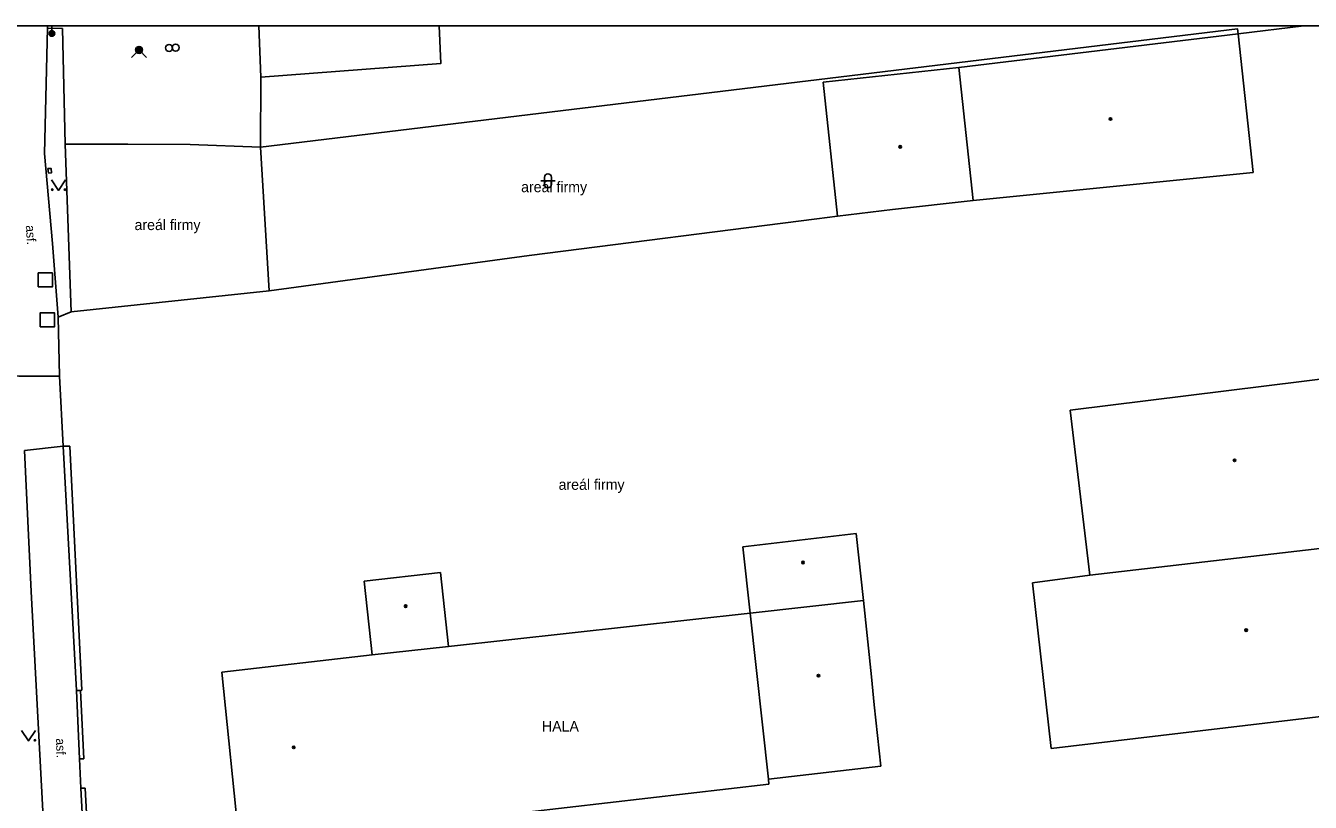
# Model space of a CAD drawing. Extents: x -599951 to -598963, y -1164095 to -1162939.
# Drawn here: x -599227.9 to -599136.7, y -1162994.5 to -1162939.4 of the extents above; entities that cross this region are included whole.
import ezdxf

# ---------------------------------------------------------------- set-up
doc = ezdxf.new("R2010")
doc.units = 0
for name, color, linetype in [('Level 10', 7, 'Continuous'), ('Level 11', 7, 'Continuous'), ('Level 24', 7, 'Continuous'), ('Level 26', 7, 'Continuous'), ('Level 28', 7, 'Continuous'), ('Level 31', 7, 'Continuous'), ('Level 33', 7, 'Continuous'), ('Level 36', 7, 'Continuous'), ('Level 39', 7, 'Continuous'), ('Level 40', 7, 'Continuous'), ('Level 41', 7, 'Continuous'), ('Level 42', 7, 'Continuous'), ('Level 5', 7, 'Continuous'), ('Level 51', 7, 'Continuous'), ('Level 52', 7, 'Continuous'), ('Level 7', 7, 'Continuous'), ('Level 8', 7, 'Continuous'), ('Vrstva 53', 7, 'Continuous')]:
    doc.layers.add(name, color=color, linetype=linetype)

msp = doc.modelspace()

# ---------------------------------------------------------------- linework, layer by layer
at = {"layer": 'Level 10'}
msp.add_line((-599226.356, -1162939.4), (-599226.36, -1162939.58), dxfattribs=at)
for points in [[(-599226.36, -1162939.58), (-599225.29, -1162939.6), (-599225.09, -1162947.8)], [(-599225.5, -1162964.29), (-599228.38, -1162964.28), (-599229.19, -1162964.24)], [(-599225.23, -1162969.24), (-599227.97, -1162969.57)]]:
    msp.add_lwpolyline(points, dxfattribs=at)
at = {"layer": 'Level 11'}
for points in [[(-599226.36, -1162939.58), (-599226.38, -1162940.54), (-599226.55, -1162948.47)], [(-599211.21, -1162943.06), (-599198.43, -1162942.09), (-599198.548, -1162939.4)], [(-599226.55, -1162948.47), (-599225.99, -1162954.86)], [(-599227.97, -1162969.57), (-599227.51, -1162979.56), (-599226.57, -1162997.39)]]:
    msp.add_lwpolyline(points, dxfattribs=at)
at = {"layer": 'Level 24'}
for points in [[(-599226.32, -1162949.55), (-599226.1, -1162949.53), (-599226.07, -1162949.85), (-599226.28, -1162949.87)], [(-599226.32, -1162949.55), (-599226.28, -1162949.87)]]:
    msp.add_lwpolyline(points, dxfattribs=at)
at = {"layer": 'Level 26'}
for points in [[(-599227, -1162957.95), (-599226, -1162957.95), (-599226, -1162956.95), (-599227, -1162956.95)], [(-599226.86, -1162960.78), (-599225.86, -1162960.78), (-599225.86, -1162959.78), (-599226.86, -1162959.78)]]:
    msp.add_lwpolyline(points, close=True, dxfattribs=at)
at = {"layer": 'Level 28'}
for centre in [(-599217.72, -1162940.98), (-599217.25, -1162940.96)]:
    msp.add_circle(centre, 0.25, dxfattribs=at)
at = {"layer": 'Level 31'}
msp.add_lwpolyline([(-599220.38, -1162941.65), (-599219.85, -1162941.12), (-599219.32, -1162941.65)], dxfattribs=at)
for radius in [0.25, 0.18, 0.11]:
    msp.add_circle((-599219.85, -1162941.12), radius, dxfattribs=at)
at = {"layer": 'Level 33'}
msp.add_line((-599226.03, -1162939.4), (-599226.03, -1162939.95), dxfattribs=at)
for radius in [0.2, 0.145, 0.0876]:
    msp.add_circle((-599226.03, -1162939.95), radius, dxfattribs=at)
at = {"layer": 'Level 36'}
for p, q in [((-599191.326, -1162950.416), (-599190.326, -1162950.416)), ((-599191.076, -1162950.166), (-599191.076, -1162950.666)), ((-599190.576, -1162950.166), (-599190.576, -1162950.666))]:
    msp.add_line(p, q, dxfattribs=at)
for points in [[(-599226.06, -1162950.34), (-599225.56, -1162951.09), (-599225.06, -1162950.34)], [(-599228.19, -1162989.43), (-599227.69, -1162990.18), (-599227.19, -1162989.43)]]:
    msp.add_lwpolyline(points, dxfattribs=at)
for centre in [(-599226.01, -1162951.04), (-599225.111, -1162951.04), (-599227.241, -1162990.13)]:
    msp.add_circle(centre, 0.05, dxfattribs=at)
for centre, start, end in [((-599190.826, -1162950.166), 0, 180), ((-599190.826, -1162950.666), 180, 0)]:
    msp.add_arc(centre, 0.25, start, end, dxfattribs=at)
at = {"layer": 'Level 39'}
for centre, radius in [((-599150.9, -1162946.02), 0.09), ((-599150.9, -1162946.02), 0.0398), ((-599165.82, -1162948), 0.09), ((-599165.82, -1162948), 0.0398), ((-599142.09, -1162970.26), 0.09), ((-599142.09, -1162970.26), 0.0398), ((-599172.72, -1162977.51), 0.09), ((-599172.72, -1162977.51), 0.0398), ((-599200.93, -1162980.61), 0.09), ((-599200.93, -1162980.61), 0.0398), ((-599141.27, -1162982.31), 0.09), ((-599141.27, -1162982.31), 0.0398), ((-599171.62, -1162985.54), 0.09), ((-599171.62, -1162985.54), 0.0398), ((-599208.87, -1162990.63), 0.09), ((-599208.87, -1162990.63), 0.0398)]:
    msp.add_circle(centre, radius, dxfattribs=at)
at = {"layer": 'Level 5'}
for points in [[(-599177, -1162976.4), (-599168.94, -1162975.45)], [(-599168.94, -1162975.45), (-599168.43, -1162980.21)], [(-599176.48, -1162981.1), (-599177, -1162976.4)], [(-599203.88, -1162978.83), (-599198.45, -1162978.23)], [(-599198.45, -1162978.23), (-599197.88, -1162983.47)], [(-599203.3, -1162984.07), (-599203.88, -1162978.83)], [(-599176.48, -1162981.1), (-599168.43, -1162980.21)], [(-599168.43, -1162980.21), (-599167.85, -1162985.62)], [(-599197.88, -1162983.47), (-599176.48, -1162981.1)], [(-599176.48, -1162981.1), (-599175.17, -1162992.89)], [(-599203.3, -1162984.07), (-599197.88, -1162983.47)], [(-599213.97, -1162985.29), (-599203.3, -1162984.07)], [(-599213.97, -1162985.29), (-599212.72, -1162997.59)], [(-599167.85, -1162985.62), (-599167.67, -1162987.62)], [(-599167.67, -1162987.62), (-599167.2, -1162991.97)], [(-599167.2, -1162991.97), (-599175.17, -1162992.89)], [(-599175.15, -1162993.25), (-599212.36, -1162997.55), (-599212.72, -1162997.59)], [(-599175.17, -1162992.89), (-599175.15, -1162993.25)]]:
    msp.add_lwpolyline(points, dxfattribs=at)
at = {"layer": 'Level 51'}
msp.add_line((-599137.179, -1162939.4), (-599141.84, -1162939.97), dxfattribs=at)
for points in [[(-599211.23, -1162948.02), (-599141.89, -1162939.62), (-599141.84, -1162939.97)], [(-599170.27, -1162952.93), (-599171.73, -1162953.11), (-599192.16, -1162955.72), (-599210.62, -1162958.23)]]:
    msp.add_lwpolyline(points, dxfattribs=at)
at = {"layer": 'Level 52'}
for points in [[(-599161.66, -1162942.36), (-599141.84, -1162939.97)], [(-599141.84, -1162939.97), (-599140.78, -1162949.83)], [(-599171.29, -1162943.41), (-599161.66, -1162942.36)], [(-599160.64, -1162951.81), (-599161.66, -1162942.36)], [(-599170.27, -1162952.93), (-599171.29, -1162943.41)], [(-599140.78, -1162949.83), (-599160.64, -1162951.81)], [(-599166.38, -1162952.44), (-599170.27, -1162952.93)], [(-599160.64, -1162951.81), (-599166.38, -1162952.44)], [(-599131.61, -1162963.95), (-599153.77, -1162966.7)], [(-599153.77, -1162966.7), (-599152.37, -1162978.42)], [(-599152.37, -1162978.42), (-599133.79, -1162976.25)], [(-599156.44, -1162978.95), (-599152.37, -1162978.42)], [(-599155.1, -1162990.71), (-599156.44, -1162978.95)], [(-599132.15, -1162987.99), (-599155.1, -1162990.71)]]:
    msp.add_lwpolyline(points, dxfattribs=at)
at = {"layer": 'Level 7'}
msp.add_line((-599211.21, -1162943.06), (-599211.356, -1162939.4), dxfattribs=at)
for points in [[(-599211.21, -1162943.06), (-599211.23, -1162948.02)], [(-599220.64, -1162947.82), (-599225.09, -1162947.8)], [(-599225.09, -1162947.8), (-599224.67, -1162959.71)], [(-599211.23, -1162948.02), (-599210.62, -1162958.23), (-599224.67, -1162959.71)], [(-599211.23, -1162948.02), (-599216.22, -1162947.83)], [(-599225.99, -1162954.86), (-599225.6, -1162960.1)], [(-599224.67, -1162959.71), (-599225.6, -1162960.1)], [(-599225.6, -1162960.1), (-599225.5, -1162964.29)], [(-599224.3, -1162986.6), (-599225.23, -1162969.24)], [(-599225.23, -1162969.24), (-599224.76, -1162969.24)], [(-599224.76, -1162969.24), (-599223.9, -1162986.58)], [(-599223.9, -1162986.58), (-599224, -1162986.59), (-599224.3, -1162986.6)], [(-599224.07, -1162991.46), (-599224.3, -1162986.6)], [(-599224, -1162986.59), (-599223.77, -1162991.45)], [(-599224.07, -1162991.46), (-599223.77, -1162991.45)], [(-599223.98, -1162993.54), (-599223.68, -1162993.52)], [(-599223.31, -1163005.98), (-599223.98, -1162993.54)], [(-599223.68, -1162993.52), (-599223.01, -1163005.96)]]:
    msp.add_lwpolyline(points, dxfattribs=at)
at = {"layer": 'Level 8'}
for points in [[(-599220.64, -1162947.82), (-599216.22, -1162947.83)], [(-599225.5, -1162964.29), (-599225.23, -1162969.24)], [(-599224.07, -1162991.46), (-599223.98, -1162993.54)]]:
    msp.add_lwpolyline(points, dxfattribs=at)
at = {"layer": 'Vrstva 53'}
msp.add_lwpolyline([(-599951.125, -1164094.695), (-598963.215, -1164094.695), (-598963.215, -1162939.4), (-599951.125, -1162939.4)], close=True, dxfattribs=at)

# ---------------------------------------------------------------- texts
at = {"layer": 'Level 40'}
for rotation, p in [(273.39684, (-599227.89, -1162953.58)), (272, (-599225.75, -1162990))]:
    msp.add_text('asf.', height=0.65, rotation=rotation, dxfattribs=at).set_placement(p)
at = {"layer": 'Level 41'}
msp.add_text('HALA', height=0.75, dxfattribs=at).set_placement((-599191.25, -1162989.51))
at = {"layer": 'Level 42'}
for p in [(-599192.73, -1162951.22), (-599220.17, -1162953.91), (-599190.07, -1162972.35)]:
    msp.add_text('areál firmy', height=0.75, dxfattribs=at).set_placement(p)

doc.saveas('drawing.dxf')
